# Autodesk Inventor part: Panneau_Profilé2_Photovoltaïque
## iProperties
Created: 2009-02
Part Number: Panneau_Profilé2_Photovoltaïque
Document SubType Name: Modeling
Designer: claivier
Author: claivier
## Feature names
1. Extrusion1
2. Perçage1 [Hole]
3. Extrusion3
